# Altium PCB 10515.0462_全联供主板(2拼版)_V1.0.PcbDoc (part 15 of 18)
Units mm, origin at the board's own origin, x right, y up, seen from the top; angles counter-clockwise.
Board outline 282 x 198 mm, 2 copper layers (Top Layer, Bottom Layer); 716 components, 0 nets, 2364 pads, 1800 vias.
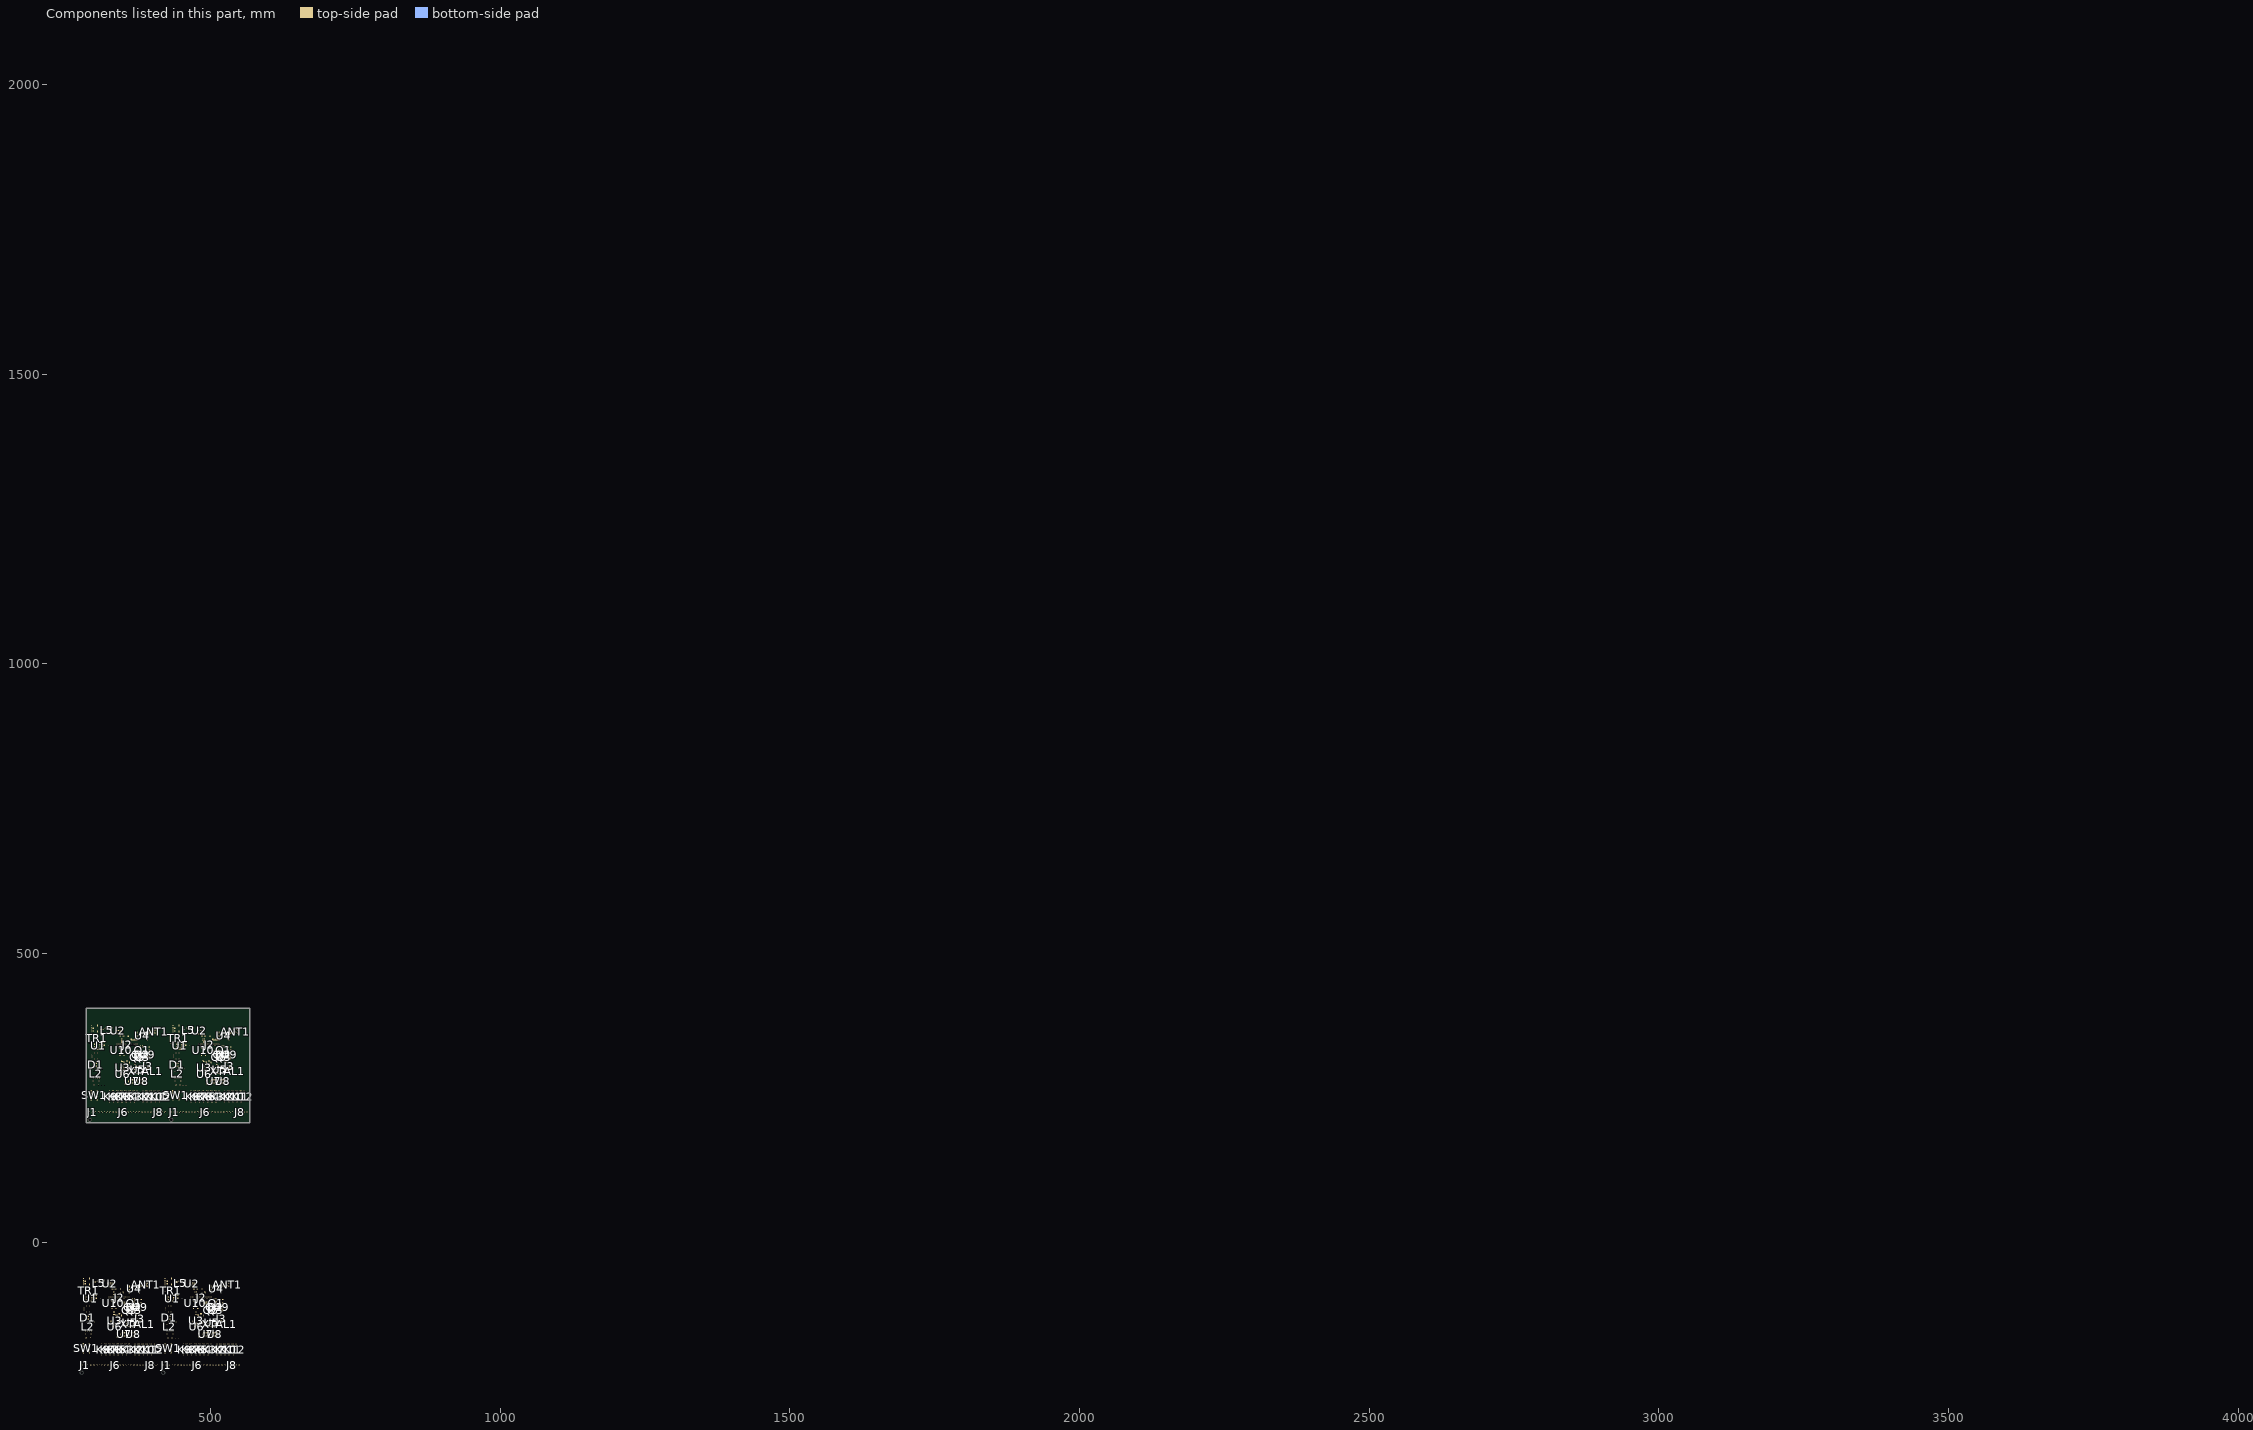
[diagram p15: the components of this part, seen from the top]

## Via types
v1: diameter 0.7, hole 0.4, Top Layer to Bottom Layer, tented both sides, 1800 vias

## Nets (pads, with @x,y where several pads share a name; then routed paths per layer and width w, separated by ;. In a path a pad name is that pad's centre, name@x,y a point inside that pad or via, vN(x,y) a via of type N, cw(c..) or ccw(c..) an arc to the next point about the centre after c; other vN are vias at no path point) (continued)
copper on no net: (continued)
  Bottom Layer w0.65: v1@318.496,-69.089 ccw(c318.496,-68.238) v1@319.098,-68.84 ; v1@318.514,-69.096 ccw(c318.952,-68.658) 318.952,-69.278 ; v1@319.154,-68.797 ccw(c319.893,-68.47) v1(319.893,-69.278) ; v1@319.87,-69.288 ccw(c319.131,-69.615) v1(319.131,-68.807) ; v1@319.875,-69.295 cw(c318.606,-70.565) 320.401,-70.565 ; v1@319.894,-69.303 cw(c319.945,-70.242) 320.61,-69.577 ; v1@320.094,-69.061 ccw(c320.386,-68.769) v1@320.64,-69.094 ; 320.401,-69.788 cw(c321.329,-69.788) v1@320.673,-69.132 ; 322.272,-92.736 cw(c322.272,-95.564) 324.272,-93.564 ccw(c323.526,-94.31) 323.526,-93.255 ccw(c323.526,-92.2) 324.272,-92.946 cw(c322.327,-91.002) 322.327,-93.752 ; 323.841,-92.736 cw(c323.841,-93.995) 324.732,-93.105 ; 323.896,-93.752 ccw(c323.896,-92.571) 324.732,-93.406 ; 324.062,-92.736 321.163,-92.736 320.401,-91.974 320.401,-69.368 319.84,-68.807 v1(319.131,-68.807) ; 324.272,-95.486 ccw(c323.526,-94.74) 324.581,-94.74 ccw(c325.636,-94.74) 324.89,-95.486 ; 324.581,-95.795 324.581,-94.376 323.957,-93.752 320.782,-93.752 319.893,-92.863 319.893,-92.355 ; 324.581,-93.255 320.794,-93.255 319.893,-92.355 ; 325.862,-95.911 327.121,-97.17 ; 327.121,-96.232 cw(c327.121,-97.287) 327.867,-96.541 cw(c328.613,-95.795) 327.558,-95.795 ; 327.259,-96.546 328.529,-97.816 ; 327.558,-95.812 ccw(c329.833,-95.9) 328.223,-97.51 ; 331.704,-92.759 331.704,-89.815 332.657,-88.862 340.15,-88.862 ; 331.704,-92.57 ccw(c332.886,-92.57) 332.05,-93.406 ; 331.704,-91.001 ccw(c334.456,-91.001) 332.51,-92.946 cw(c333.256,-92.2) 332.201,-92.2 cw(c331.146,-92.2) 331.892,-92.946 ccw(c330.353,-91.407) 332.53,-91.407 ; v1@332.125,367.506 ccw(c332.125,368.358) v1@332.727,367.756 ; v1@332.143,367.499 ccw(c332.581,367.937) 332.581,367.318 ; 332.201,-93.255 332.201,-91.974 332.201,-90.588 ; 332.53,-92.927 332.53,-90.259 ; v1@332.783,367.799 ccw(c333.522,368.126) v1(333.522,367.318) ; v1@333.499,367.308 ccw(c332.76,366.981) v1(332.76,367.789) ; v1@333.504,367.3 cw(c332.235,366.031) 334.03,366.031 ; v1@333.523,367.293 cw(c333.574,366.354) 334.239,367.019 ; v1@333.723,367.535 ccw(c334.015,367.827) v1@334.269,367.501 ; 334.03,366.808 cw(c334.957,366.808) v1@334.302,367.464 ; 334.741,-93.255 334.741,-91.477 334.752,-91.466 ; 335.901,343.859 cw(c335.901,341.031) 337.901,343.031 ccw(c337.155,342.285) 337.155,343.34 ccw(c337.155,344.395) 337.901,343.649 cw(c335.956,345.594) 335.956,342.843 ; 337.47,343.859 cw(c337.47,342.6) 338.36,343.491 ; 337.525,342.843 ccw(c337.525,344.025) 338.36,343.189 ; 337.69,343.859 334.792,343.859 334.03,344.621 334.03,367.227 333.469,367.789 v1(332.76,367.789) ; 337.901,341.109 ccw(c337.155,341.855) 338.21,341.855 ccw(c339.265,341.855) 338.519,341.109 ; 338.21,340.8 338.21,342.22 337.586,342.843 334.411,342.843 333.522,343.732 333.522,344.24 ; 338.21,343.34 334.422,343.34 333.522,344.24 ; 339.324,-89.688 340.15,-88.862 ; 339.491,340.684 340.75,339.426 ; 340.14,-88.872 cw(c341.483,-90.216) v1@341.483,-88.316 ; 340.467,-89.307 341.737,-88.037 ; v1@340.729,-88.267 ccw(c341.05,-87.35) 341.737,-88.037 ; 340.75,340.363 cw(c340.75,339.308) 341.496,340.054 cw(c342.242,340.8) 341.187,340.8 ; 340.888,340.049 342.158,338.779 ; 340.902,-88.872 cw(c342.245,-90.216) v1@342.245,-88.316 ; v1@340.902,-88.11 cw(c342.245,-89.454) v1@342.245,-87.554 ; 340.912,-88.862 ccw(c339.569,-87.518) v1@341.469,-87.518 ; 341.186,340.783 ccw(c343.461,340.696) 341.852,339.086 ; v1@341.356,-88.418 cw(c341.861,-88.923) v1@342.232,-88.312 ; v1@341.465,-88.273 ccw(c340.81,-87.617) v1@341.737,-87.617 ; v1@341.468,-88.311 cw(c341.045,-88.859) 341.737,-88.859 ; v1@341.476,-87.536 cw(c340.846,-88.167) v1@341.737,-88.167 ; v1@341.508,-88.291 cw(c343.408,-88.291) v1@342.065,-86.948 ; 341.737,-89.009 cw(c342.463,-89.009) v1@342.252,-88.315 ; v1@341.737,-88.247 cw(c342.463,-88.247) v1@342.252,-87.553 ; 341.801,-89.37 ccw(c340.785,-88.354) v1@342.22,-88.292 ; v1@342.259,-88.27 cw(c342.947,-87.275) v1@341.737,-87.275 ; 345.333,343.837 345.333,346.78 346.285,347.733 353.778,347.733 ; 345.333,344.025 ccw(c346.515,344.025) 345.679,343.189 ; 345.333,345.595 ccw(c348.084,345.595) 346.139,343.649 cw(c346.885,344.395) 345.83,344.395 cw(c344.775,344.395) 345.521,343.649 ccw(c343.981,345.188) 346.158,345.188 ; 345.83,343.34 345.83,344.621 345.83,346.007 ; 346.158,343.669 346.158,346.336 ; v1(347.452,-128.11) 347.497,-128.155 352.926,-128.155 376.027,-128.155 ; 348.37,343.34 348.37,345.118 348.381,345.129 ; v1(348.883,-103.669) v1(352.439,-103.669) 356.735,-103.669 357.231,-104.166 357.231,-113.31 357.231,-113.564 ; v1(348.96,-101.941) v1(352.389,-101.941) v1(355.945,-101.941) 357.866,-101.941 ; 352.953,346.907 353.778,347.733 ; 353.768,347.723 cw(c355.112,346.38) v1@355.112,348.279 ; 354.096,347.288 355.366,348.558 ; v1@354.358,348.328 ccw(c354.679,349.246) 355.366,348.558 ; 354.53,347.723 cw(c355.874,346.38) v1@355.874,348.279 ; v1@354.53,348.485 cw(c355.874,347.142) v1@355.874,349.041 ; 354.541,347.734 ccw(c353.197,349.077) v1@355.097,349.077 ; v1@354.985,348.178 cw(c355.49,347.672) v1@355.861,348.283 ; v1@355.094,348.322 ccw(c354.438,348.978) v1@355.366,348.978 ; v1@355.097,348.285 cw(c354.673,347.737) 355.366,347.737 ; v1@355.105,349.059 cw(c354.474,348.429) v1@355.366,348.429 ; v1@355.137,348.304 cw(c357.037,348.304) v1@355.693,349.648 ; 355.366,347.586 cw(c356.092,347.586) v1@355.881,348.281 ; v1@355.366,348.348 cw(c356.092,348.348) v1@355.881,349.043 ; v1@355.366,349.32 ccw(c356.576,349.32) v1@355.888,348.325 ; 355.429,347.225 ccw(c354.413,348.241) v1@355.849,348.303 ; v1(355.961,-103.658) 356.215,-103.658 357.231,-104.674 ; 358.755,-113.008 cw(c360.098,-113.008) v1@359.149,-112.058 ; 358.755,-111.072 ccw(c360.098,-111.072) v1@359.149,-112.022 ; 358.755,-106.553 cw(c360.14,-106.553) v1@359.161,-105.574 ; 358.755,-104.559 ccw(c360.14,-104.559) v1@359.161,-105.538 ; v1(359.131,-112.04) 359.131,-112.162 360.279,-113.31 ; v1(361.081,308.486) 361.126,308.44 366.555,308.44 389.656,308.44 ; v1(362.512,332.926) v1(366.068,332.926) 370.363,332.926 370.86,332.429 370.86,323.285 370.86,323.031 ; 362.565,-98.324 361.25,-98.324 360.742,-97.816 ; v1(362.589,334.654) v1(366.018,334.654) v1(369.574,334.654) 371.495,334.654 ; 362.819,-127.026 363.581,-126.264 ; 363.199,-127.16 363.581,-126.777 ; v1(363.581,-127.28) 363.581,-126.645 ; 363.581,-120.676 363.581,-120.644 364.184,-120.041 ; 363.581,-119.279 363.581,-119.438 364.184,-120.041 ; 363.964,-127.147 363.594,-126.777 363.581,-126.777 ; 364.47,-127.039 364.356,-127.039 363.581,-126.264 ; 364.548,-113.31 cw(c364.548,-115.491) v1@366.089,-113.949 ; 364.964,-113.31 366.107,-114.453 ; 365.225,-113.571 ccw(c366.039,-112.758) v1@366.106,-113.906 ; v1(365.232,-120.041) 364.216,-120.041 ; v1@365.468,-122.7 cw(c363.927,-124.242) 366.107,-124.242 ; v1@365.468,-122.664 ccw(c363.927,-121.122) 366.107,-121.122 ; v1(366.107,-126.264) 366.107,-118.263 ; 366.107,-119.279 366.107,-119.166 367.01,-118.263 ; 366.107,-117.374 366.996,-118.263 367.01,-118.263 ; v1@366.107,-113.906 ccw(c366.107,-112.585) 367.041,-113.519 ; 366.107,-113.451 v1(366.107,-113.931) 366.107,-114.453 ; v1@366.125,-113.949 cw(c367.667,-115.491) 367.667,-113.31 ; 367.25,-113.31 366.107,-114.453 ; v1(369.59,332.937) 369.844,332.937 370.86,331.921 ; v1(369.931,-113.31) 359.639,-113.31 ; v1(370.727,-117.12) 370.806,-117.041 370.806,-111.038 371.438,-110.406 v1(373.597,-110.406) ; 372.384,323.588 cw(c373.727,323.588) v1@372.777,324.538 ; 372.384,325.523 ccw(c373.727,325.523) v1@372.777,324.573 ; 372.384,330.042 cw(c373.769,330.042) v1@372.79,331.022 ; 372.384,332.037 ccw(c373.769,332.037) v1@372.79,331.057 ; v1(372.76,324.555) 372.76,324.434 373.908,323.285 ; v1(373.614,-112.057) 372.327,-112.057 371.836,-112.548 371.836,-118.009 371.582,-118.263 v1(369.804,-118.263) 367.01,-118.263 ; 374.59,-128.155 cw(c374.59,-130.342) v1@376.136,-128.796 ; v1@376.154,-128.803 cw(c376.154,-130.553) 377.392,-129.316 ; 376.194,338.271 374.879,338.271 374.371,338.779 ; 376.448,309.569 377.21,310.331 ; 376.827,309.436 377.21,309.818 ; 377.152,-130.795 377.152,-129.076 ; 377.152,-129.166 ccw(c379.508,-129.166) 377.842,-130.831 cw(c378.631,-130.042) 377.515,-130.042 cw(c376.399,-130.042) 377.188,-130.831 ; v1(377.21,309.315) 377.21,309.95 ; 377.21,315.919 377.21,315.952 377.813,316.554 ; 377.21,317.316 377.21,317.157 377.813,316.554 ; 377.515,-131.158 377.515,-128.895 376.775,-128.155 376.027,-128.155 ; 377.515,-129.439 377.152,-129.076 ; 377.592,309.449 377.223,309.818 377.21,309.818 ; 378.099,309.556 377.985,309.556 377.21,310.331 ; 378.176,323.285 cw(c378.176,321.105) v1@379.718,322.647 ; 378.593,323.285 379.736,322.142 ; 378.854,323.024 ccw(c379.667,323.838) v1@379.734,322.689 ; v1(378.861,316.554) 377.845,316.554 ; v1@379.097,313.896 cw(c377.555,312.354) 379.736,312.354 ; v1@379.097,313.931 ccw(c377.555,315.473) 379.736,315.473 ; v1(379.736,310.331) 379.736,318.332 ; 379.736,317.316 379.736,317.429 380.639,318.332 ; 379.736,319.221 380.625,318.332 380.639,318.332 ; v1@379.736,322.689 ccw(c379.736,324.01) 380.67,323.076 ; 379.736,323.144 v1(379.736,322.664) 379.736,322.142 ; v1@379.754,322.647 cw(c381.295,321.105) 381.295,323.285 ; v1(379.78,-109.754) 379.78,-106.706 379.78,-102.065 v1(380.091,-101.753) ; 379.78,-102.566 cw(c380.904,-102.566) v1@380.109,-101.771 ; 380.879,323.285 379.736,322.142 ; v1(383.56,323.285) 373.268,323.285 ; v1(384.356,319.475) 384.435,319.555 384.435,325.557 385.067,326.19 v1(387.226,326.19) ; v1(387.243,324.539) 385.956,324.539 385.465,324.047 385.465,318.586 385.211,318.332 v1(383.433,318.332) 380.639,318.332 ; 388.218,308.44 cw(c388.218,306.253) v1@389.765,307.8 ; v1@389.783,307.792 cw(c389.783,306.042) 391.02,307.28 ; 390.781,305.8 390.781,307.519 ; 390.781,307.43 ccw(c393.136,307.43) 391.471,305.764 cw(c392.26,306.553) 391.144,306.553 cw(c390.027,306.553) 390.817,305.764 ; 391.144,305.437 391.144,307.701 390.404,308.44 389.656,308.44 ; 391.144,307.156 390.781,307.519 ; v1(393.408,326.841) 393.408,329.889 393.408,334.531 v1(393.72,334.842) ; 393.408,334.03 cw(c394.533,334.03) v1@393.738,334.825 ; v1@459.496,-69.089 ccw(c459.496,-68.238) v1@460.098,-68.84 ; v1@459.514,-69.096 ccw(c459.952,-68.658) 459.952,-69.278 ; v1@460.154,-68.797 ccw(c460.893,-68.47) v1(460.893,-69.278) ; v1@460.87,-69.288 ccw(c460.131,-69.615) v1(460.131,-68.807) ; v1@460.875,-69.295 cw(c459.606,-70.565) 461.401,-70.565 ; v1@460.894,-69.303 cw(c460.945,-70.242) 461.61,-69.577 ; v1@461.094,-69.061 ccw(c461.386,-68.769) v1@461.64,-69.094 ; 461.401,-69.788 cw(c462.329,-69.788) v1@461.673,-69.132 ; 463.272,-92.736 cw(c463.272,-95.564) 465.272,-93.564 ccw(c464.526,-94.31) 464.526,-93.255 ccw(c464.526,-92.2) 465.272,-92.946 cw(c463.327,-91.002) 463.327,-93.752 ; 464.841,-92.736 cw(c464.841,-93.995) 465.732,-93.105 ; 464.896,-93.752 ccw(c464.896,-92.571) 465.732,-93.406 ; 465.062,-92.736 462.163,-92.736 461.401,-91.974 461.401,-69.368 460.84,-68.807 v1(460.131,-68.807) ; 465.272,-95.486 ccw(c464.526,-94.74) 465.581,-94.74 ccw(c466.636,-94.74) 465.89,-95.486 ; 465.581,-95.795 465.581,-94.376 464.957,-93.752 461.782,-93.752 460.893,-92.863 460.893,-92.355 ; 465.581,-93.255 461.794,-93.255 460.893,-92.355 ; 466.862,-95.911 468.121,-97.17 ; 468.121,-96.232 cw(c468.121,-97.287) 468.867,-96.541 cw(c469.613,-95.795) 468.558,-95.795 ; 468.259,-96.546 469.529,-97.816 ; 468.558,-95.812 ccw(c470.833,-95.9) 469.223,-97.51 ; 472.704,-92.759 472.704,-89.815 473.657,-88.862 481.15,-88.862 ; 472.704,-92.57 ccw(c473.886,-92.57) 473.05,-93.406 ; 472.704,-91.001 ccw(c475.456,-91.001) 473.51,-92.946 cw(c474.256,-92.2) 473.201,-92.2 cw(c472.146,-92.2) 472.892,-92.946 ccw(c471.353,-91.407) 473.53,-91.407 ; v1@473.125,367.506 ccw(c473.125,368.358) v1@473.727,367.756 ; v1@473.143,367.499 ccw(c473.581,367.937) 473.581,367.318 ; 473.201,-93.255 473.201,-91.974 473.201,-90.588 ; 473.53,-92.927 473.53,-90.259 ; v1@473.783,367.799 ccw(c474.522,368.126) v1(474.522,367.318) ; v1@474.499,367.308 ccw(c473.76,366.981) v1(473.76,367.789) ; v1@474.504,367.3 cw(c473.235,366.031) 475.03,366.031 ; v1@474.523,367.293 cw(c474.574,366.354) 475.239,367.019 ; v1@474.723,367.535 ccw(c475.015,367.827) v1@475.269,367.501 ; 475.03,366.808 cw(c475.957,366.808) v1@475.302,367.464 ; 475.741,-93.255 475.741,-91.477 475.752,-91.466 ; 476.901,343.859 cw(c476.901,341.031) 478.901,343.031 ccw(c478.155,342.285) 478.155,343.34 ccw(c478.155,344.395) 478.901,343.649 cw(c476.956,345.594) 476.956,342.843 ; 478.47,343.859 cw(c478.47,342.6) 479.36,343.491 ; 478.525,342.843 ccw(c478.525,344.025) 479.36,343.189 ; 478.69,343.859 475.792,343.859 475.03,344.621 475.03,367.227 474.469,367.789 v1(473.76,367.789) ; 478.901,341.109 ccw(c478.155,341.855) 479.21,341.855 ccw(c480.265,341.855) 479.519,341.109 ; 479.21,340.8 479.21,342.22 478.586,342.843 475.411,342.843 474.522,343.732 474.522,344.24 ; 479.21,343.34 475.422,343.34 474.522,344.24 ; 480.324,-89.688 481.15,-88.862 ; 480.491,340.684 481.75,339.426 ; 481.14,-88.872 cw(c482.483,-90.216) v1@482.483,-88.316 ; 481.467,-89.307 482.737,-88.037 ; v1@481.729,-88.267 ccw(c482.05,-87.35) 482.737,-88.037 ; 481.75,340.363 cw(c481.75,339.308) 482.496,340.054 cw(c483.242,340.8) 482.187,340.8 ; 481.888,340.049 483.158,338.779 ; 481.902,-88.872 cw(c483.245,-90.216) v1@483.245,-88.316 ; v1@481.902,-88.11 cw(c483.245,-89.454) v1@483.245,-87.554 ; 481.912,-88.862 ccw(c480.569,-87.518) v1@482.469,-87.518 ; 482.186,340.783 ccw(c484.461,340.696) 482.852,339.086 ; v1@482.356,-88.418 cw(c482.861,-88.923) v1@483.232,-88.312 ; v1@482.465,-88.273 ccw(c481.81,-87.617) v1@482.737,-87.617 ; v1@482.468,-88.311 cw(c482.045,-88.859) 482.737,-88.859 ; v1@482.476,-87.536 cw(c481.846,-88.167) v1@482.737,-88.167 ; v1@482.508,-88.291 cw(c484.408,-88.291) v1@483.065,-86.948 ; 482.737,-89.009 cw(c483.463,-89.009) v1@483.252,-88.315 ; v1@482.737,-88.247 cw(c483.463,-88.247) v1@483.252,-87.553 ; 482.801,-89.37 ccw(c481.785,-88.354) v1@483.22,-88.292 ; v1@483.259,-88.27 cw(c483.947,-87.275) v1@482.737,-87.275 ; 486.333,343.837 486.333,346.78 487.285,347.733 494.778,347.733 ; 486.333,344.025 ccw(c487.515,344.025) 486.679,343.189 ; 486.333,345.595 ccw(c489.084,345.595) 487.139,343.649 cw(c487.885,344.395) 486.83,344.395 cw(c485.775,344.395) 486.521,343.649 ccw(c484.981,345.188) 487.158,345.188 ; 486.83,343.34 486.83,344.621 486.83,346.007 ; 487.158,343.669 487.158,346.336 ; v1(488.452,-128.11) 488.497,-128.155 493.926,-128.155 517.027,-128.155 ; 489.37,343.34 489.37,345.118 489.381,345.129 ; v1(489.883,-103.669) v1(493.439,-103.669) 497.735,-103.669 498.231,-104.166 498.231,-113.31 498.231,-113.564 ; v1(489.96,-101.941) v1(493.389,-101.941) v1(496.945,-101.941) 498.866,-101.941 ; 493.953,346.907 494.778,347.733 ; 494.768,347.723 cw(c496.112,346.38) v1@496.112,348.279 ; 495.096,347.288 496.366,348.558 ; v1@495.358,348.328 ccw(c495.679,349.246) 496.366,348.558 ; 495.53,347.723 cw(c496.874,346.38) v1@496.874,348.279 ; v1@495.53,348.485 cw(c496.874,347.142) v1@496.874,349.041 ; 495.541,347.734 ccw(c494.197,349.077) v1@496.097,349.077 ; v1@495.985,348.178 cw(c496.49,347.672) v1@496.861,348.283 ; v1@496.094,348.322 ccw(c495.438,348.978) v1@496.366,348.978 ; v1@496.097,348.285 cw(c495.673,347.737) 496.366,347.737 ; v1@496.105,349.059 cw(c495.474,348.429) v1@496.366,348.429 ; v1@496.137,348.304 cw(c498.037,348.304) v1@496.693,349.648 ; 496.366,347.586 cw(c497.092,347.586) v1@496.881,348.281 ; v1@496.366,348.348 cw(c497.092,348.348) v1@496.881,349.043 ; v1@496.366,349.32 ccw(c497.576,349.32) v1@496.888,348.325 ; 496.429,347.225 ccw(c495.413,348.241) v1@496.849,348.303 ; v1(496.961,-103.658) 497.215,-103.658 498.231,-104.674 ; 499.755,-113.008 cw(c501.098,-113.008) v1@500.149,-112.058 ; 499.755,-111.072 ccw(c501.098,-111.072) v1@500.149,-112.022 ; 499.755,-106.553 cw(c501.14,-106.553) v1@500.161,-105.574 ; 499.755,-104.559 ccw(c501.14,-104.559) v1@500.161,-105.538 ; v1(500.131,-112.04) 500.131,-112.162 501.279,-113.31 ; v1(502.081,308.486) 502.126,308.44 507.555,308.44 530.656,308.44 ; v1(503.512,332.926) v1(507.068,332.926) 511.363,332.926 511.86,332.429 511.86,323.285 511.86,323.031 ; 503.565,-98.324 502.25,-98.324 501.742,-97.816 ; v1(503.589,334.654) v1(507.018,334.654) v1(510.574,334.654) 512.495,334.654 ; 503.819,-127.026 504.581,-126.264 ; 504.199,-127.16 504.581,-126.777 ; v1(504.581,-127.28) 504.581,-126.645 ; 504.581,-120.676 504.581,-120.644 505.184,-120.041 ; 504.581,-119.279 504.581,-119.438 505.184,-120.041 ; 504.964,-127.147 504.594,-126.777 504.581,-126.777 ; 505.47,-127.039 505.356,-127.039 504.581,-126.264 ; 505.548,-113.31 cw(c505.548,-115.491) v1@507.089,-113.949 ; 505.964,-113.31 507.107,-114.453 ; 506.225,-113.571 ccw(c507.039,-112.758) v1@507.106,-113.906 ; v1(506.232,-120.041) 505.216,-120.041 ; v1@506.468,-122.7 cw(c504.927,-124.242) 507.107,-124.242 ; v1@506.468,-122.664 ccw(c504.927,-121.122) 507.107,-121.122 ; v1(507.107,-126.264) 507.107,-118.263 ; 507.107,-119.279 507.107,-119.166 508.01,-118.263 ; 507.107,-117.374 507.996,-118.263 508.01,-118.263 ; v1@507.107,-113.906 ccw(c507.107,-112.585) 508.041,-113.519 ; 507.107,-113.451 v1(507.107,-113.931) 507.107,-114.453 ; v1@507.125,-113.949 cw(c508.667,-115.491) 508.667,-113.31 ; 508.25,-113.31 507.107,-114.453 ; v1(510.59,332.937) 510.844,332.937 511.86,331.921 ; v1(510.931,-113.31) 500.639,-113.31 ; v1(511.727,-117.12) 511.806,-117.041 511.806,-111.038 512.438,-110.406 v1(514.597,-110.406) ; 513.384,323.588 cw(c514.727,323.588) v1@513.777,324.538 ; 513.384,325.523 ccw(c514.727,325.523) v1@513.777,324.573 ; 513.384,330.042 cw(c514.769,330.042) v1@513.79,331.022 ; 513.384,332.037 ccw(c514.769,332.037) v1@513.79,331.057 ; v1(513.76,324.555) 513.76,324.434 514.908,323.285 ; v1(514.614,-112.057) 513.327,-112.057 512.836,-112.548 512.836,-118.009 512.582,-118.263 v1(510.804,-118.263) 508.01,-118.263 ; 515.59,-128.155 cw(c515.59,-130.342) v1@517.136,-128.796 ; v1@517.154,-128.803 cw(c517.154,-130.553) 518.392,-129.316 ; 517.194,338.271 515.879,338.271 515.371,338.779 ; 517.448,309.569 518.21,310.331 ; 517.827,309.436 518.21,309.818 ; 518.152,-130.795 518.152,-129.076 ; 518.152,-129.166 ccw(c520.508,-129.166) 518.842,-130.831 cw(c519.631,-130.042) 518.515,-130.042 cw(c517.399,-130.042) 518.188,-130.831 ; v1(518.21,309.315) 518.21,309.95 ; 518.21,315.919 518.21,315.952 518.813,316.554 ; 518.21,317.316 518.21,317.157 518.813,316.554 ; 518.515,-131.158 518.515,-128.895 517.775,-128.155 517.027,-128.155 ; 518.515,-129.439 518.152,-129.076 ; 518.593,309.449 518.223,309.818 518.21,309.818 ; 519.099,309.556 518.985,309.556 518.21,310.331 ; 519.176,323.285 cw(c519.176,321.105) v1@520.718,322.647 ; 519.593,323.285 520.736,322.142 ; 519.854,323.024 ccw(c520.667,323.838) v1@520.734,322.689 ; v1(519.861,316.554) 518.845,316.554 ; v1@520.097,313.896 cw(c518.555,312.354) 520.736,312.354 ; v1@520.097,313.931 ccw(c518.555,315.473) 520.736,315.473 ; v1(520.736,310.331) 520.736,318.332 ; 520.736,317.316 520.736,317.429 521.639,318.332 ; 520.736,319.221 521.625,318.332 521.639,318.332 ; v1@520.736,322.689 ccw(c520.736,324.01) 521.67,323.076 ; 520.736,323.144 v1(520.736,322.664) 520.736,322.142 ; v1@520.754,322.647 cw(c522.295,321.105) 522.295,323.285 ; v1(520.78,-109.754) 520.78,-106.706 520.78,-102.065 v1(521.091,-101.753) ; 520.78,-102.566 cw(c521.904,-102.566) v1@521.109,-101.771 ; 521.879,323.285 520.736,322.142 ; v1(524.56,323.285) 514.268,323.285 ; v1(525.356,319.475) 525.435,319.555 525.435,325.557 526.067,326.19 v1(528.226,326.19) ; v1(528.243,324.539) 526.956,324.539 526.465,324.047 526.465,318.586 526.211,318.332 v1(524.433,318.332) 521.639,318.332 ; 529.218,308.44 cw(c529.218,306.253) v1@530.765,307.8 ; v1@530.783,307.792 cw(c530.783,306.042) 532.02,307.28 ; 531.781,305.8 531.781,307.519 ; 531.781,307.43 ccw(c534.136,307.43) 532.471,305.764 cw(c533.26,306.553) 532.144,306.553 cw(c531.027,306.553) 531.817,305.764 ; 532.144,305.437 532.144,307.701 531.404,308.44 530.656,308.44 ; 532.144,307.156 531.781,307.519 ; v1(534.408,326.841) 534.408,329.889 534.408,334.531 v1(534.72,334.842) ; 534.408,334.03 cw(c535.533,334.03) v1@534.738,334.825 ; v1(319.131,-68.807) 318.66,-69.278 v1(319.893,-69.278) ; 319.893,-92.355 v1(319.893,-69.278) ; 327.121,-97.17 327.121,-95.795 329.142,-97.816 ; 327.121,-97.17 327.767,-97.816 ; 327.121,-96.85 ccw(c326.066,-96.85) 326.812,-96.104 cw(c326.066,-96.85) 327.121,-96.85 ; 327.121,-96.85 cw(c328.176,-96.85) 327.43,-96.104 ccw(c328.176,-96.85) 327.121,-96.85 ; 327.767,-97.816 328.275,-98.324 329.799,-98.324 ; 327.767,-97.816 328.529,-97.816 ; 328.529,-97.816 329.291,-97.816 ; 329.142,-97.816 360.742,-97.816 ; 329.142,-97.816 329.291,-97.816 ; 329.291,-97.816 329.799,-98.324 ; 329.799,-98.324 363.327,-98.324 ; 332.201,-90.588 332.201,-89.953 332.847,-89.307 333.482,-89.307 341.229,-89.307 341.737,-88.799 341.737,-88.037 ; 332.201,-90.588 332.53,-90.259 ; 332.53,-90.259 333.101,-89.688 341.483,-89.688 342.245,-88.926 v1(342.245,-86.767) ; v1(332.76,367.789) 332.289,367.318 v1(333.522,367.318) ; 333.522,344.24 v1(333.522,367.318) ; 340.15,-88.862 v1(342.245,-86.767) ; 340.75,339.426 340.75,340.8 342.77,338.779 ; 340.75,339.426 341.396,338.779 ; 340.75,339.745 ccw(c339.695,339.745) 340.441,340.491 cw(c339.695,339.745) 340.75,339.745 ; 340.75,339.745 cw(c341.805,339.745) 341.059,340.491 ccw(c341.805,339.745) 340.75,339.745 ; 341.396,338.779 341.904,338.271 343.428,338.271 ; 341.396,338.779 342.158,338.779 ; 341.737,-88.037 v1@341.737,-87.275 ; v1@341.737,-87.275 v1(342.245,-86.767) ; 342.158,338.779 342.92,338.779 ; 342.77,338.779 374.371,338.779 ; 342.77,338.779 342.92,338.779 ; 342.92,338.779 343.428,338.271 ; 343.428,338.271 376.956,338.271 ; 345.83,346.007 345.83,346.642 346.476,347.288 347.111,347.288 354.858,347.288 355.366,347.796 355.366,348.558 ; 345.83,346.007 346.158,346.336 ; 346.158,346.336 346.73,346.907 355.112,346.907 355.874,347.669 v1(355.874,349.828) ; 353.778,347.733 v1(355.874,349.828) ; 355.366,348.558 355.366,349.32 v1(355.874,349.828) ; 357.231,-113.564 357.231,-114.072 357.612,-114.453 358.12,-114.453 ; 357.231,-113.564 358.12,-114.453 ; 357.866,-101.941 358.69,-101.941 359.143,-102.395 v1(359.143,-105.556) 359.143,-112.814 359.639,-113.31 ; 357.866,-101.941 358.755,-102.83 358.755,-113.056 359.009,-113.31 359.639,-113.31 ; 358.12,-114.453 362.311,-114.453 362.565,-114.453 ; 360.742,-97.816 363.454,-97.816 363.962,-98.324 ; 362.565,-114.453 363.581,-115.469 ; 362.565,-114.453 363.2,-114.453 363.581,-114.834 363.581,-115.469 ; 363.327,-98.324 363.708,-98.705 v1(366.121,-101.118) 366.121,-100.483 363.962,-98.324 ; 363.327,-98.324 363.962,-98.324 ; 363.581,-126.777 363.581,-126.645 ; 363.581,-126.645 363.581,-126.264 ; 363.581,-126.264 v1(363.581,-120.041) ; v1(363.581,-120.041) 364.216,-120.041 ; v1(363.581,-120.041) 363.581,-115.469 ; 364.184,-120.041 364.216,-120.041 ; 364.184,-120.041 364.216,-120.041 ; 366.107,-118.263 367.01,-118.263 ; 366.107,-118.263 366.107,-114.453 ; 370.86,323.031 370.86,322.523 371.241,322.142 371.749,322.142 ; 370.86,323.031 371.749,322.142 ; 371.495,334.654 372.318,334.654 372.772,334.2 v1(372.772,331.039) 372.772,323.781 373.268,323.285 ; 371.495,334.654 372.384,333.765 372.384,323.539 372.638,323.285 373.268,323.285 ; 371.749,322.142 375.94,322.142 376.194,322.142 ; 374.371,338.779 377.083,338.779 377.591,338.271 ; 376.027,-128.155 376.231,-128.155 377.152,-129.076 ; 376.194,322.142 377.21,321.126 ; 376.194,322.142 376.829,322.142 377.21,321.761 377.21,321.126 ; 376.956,338.271 377.337,337.89 v1(379.75,335.477) 379.75,336.112 377.591,338.271 ; 376.956,338.271 377.591,338.271 ; 377.21,309.818 377.21,309.95 ; 377.21,309.95 377.21,310.331 ; 377.21,310.331 v1(377.21,316.554) ; v1(377.21,316.554) 377.845,316.554 ; v1(377.21,316.554) 377.21,321.126 ; 377.813,316.554 377.845,316.554 ; 377.813,316.554 377.845,316.554 ; 379.736,318.332 380.639,318.332 ; 379.736,318.332 379.736,322.142 ; 389.656,308.44 389.86,308.44 390.781,307.519 ; v1(460.131,-68.807) 459.66,-69.278 v1(460.893,-69.278) ; 460.893,-92.355 v1(460.893,-69.278) ; 468.121,-97.17 468.121,-95.795 470.142,-97.816 ; 468.121,-97.17 468.767,-97.816 ; 468.121,-96.85 ccw(c467.066,-96.85) 467.812,-96.104 cw(c467.066,-96.85) 468.121,-96.85 ; 468.121,-96.85 cw(c469.176,-96.85) 468.43,-96.104 ccw(c469.176,-96.85) 468.121,-96.85 ; 468.767,-97.816 469.275,-98.324 470.799,-98.324 ; 468.767,-97.816 469.529,-97.816 ; 469.529,-97.816 470.291,-97.816 ; 470.142,-97.816 501.742,-97.816 ; 470.142,-97.816 470.291,-97.816 ; 470.291,-97.816 470.799,-98.324 ; 470.799,-98.324 504.327,-98.324 ; 473.201,-90.588 473.201,-89.953 473.847,-89.307 474.482,-89.307 482.229,-89.307 482.737,-88.799 482.737,-88.037 ; 473.201,-90.588 473.53,-90.259 ; 473.53,-90.259 474.101,-89.688 482.483,-89.688 483.245,-88.926 v1(483.245,-86.767) ; v1(473.76,367.789) 473.289,367.318 v1(474.522,367.318) ; 474.522,344.24 v1(474.522,367.318) ; 481.15,-88.862 v1(483.245,-86.767) ; 481.75,339.426 481.75,340.8 483.77,338.779 ; 481.75,339.426 482.396,338.779 ; 481.75,339.745 ccw(c480.695,339.745) 481.441,340.491 cw(c480.695,339.745) 481.75,339.745 ; 481.75,339.745 cw(c482.805,339.745) 482.059,340.491 ccw(c482.805,339.745) 481.75,339.745 ; 482.396,338.779 482.904,338.271 484.428,338.271 ; 482.396,338.779 483.158,338.779 ; 482.737,-88.037 v1@482.737,-87.275 ; v1@482.737,-87.275 v1(483.245,-86.767) ; 483.158,338.779 483.92,338.779 ; 483.77,338.779 515.371,338.779 ; 483.77,338.779 483.92,338.779 ; 483.92,338.779 484.428,338.271 ; 484.428,338.271 517.956,338.271 ; 486.83,346.007 486.83,346.642 487.476,347.288 488.111,347.288 495.858,347.288 496.366,347.796 496.366,348.558 ; 486.83,346.007 487.158,346.336 ; 487.158,346.336 487.73,346.907 496.112,346.907 496.874,347.669 v1(496.874,349.828) ; 494.778,347.733 v1(496.874,349.828) ; 496.366,348.558 496.366,349.32 v1(496.874,349.828) ; 498.231,-113.564 498.231,-114.072 498.612,-114.453 499.12,-114.453 ; 498.231,-113.564 499.12,-114.453 ; 498.866,-101.941 499.69,-101.941 500.143,-102.395 v1(500.143,-105.556) 500.143,-112.814 500.639,-113.31 ; 498.866,-101.941 499.755,-102.83 499.755,-113.056 500.009,-113.31 500.639,-113.31 ; 499.12,-114.453 503.311,-114.453 503.565,-114.453 ; 501.742,-97.816 504.454,-97.816 504.962,-98.324 ; 503.565,-114.453 504.581,-115.469 ; 503.565,-114.453 504.2,-114.453 504.581,-114.834 504.581,-115.469 ; 504.327,-98.324 504.708,-98.705 v1(507.121,-101.118) 507.121,-100.483 504.962,-98.324 ; 504.327,-98.324 504.962,-98.324 ; 504.581,-126.777 504.581,-126.645 ; 504.581,-126.645 504.581,-126.264 ; 504.581,-126.264 v1(504.581,-120.041) ; v1(504.581,-120.041) 505.216,-120.041 ; v1(504.581,-120.041) 504.581,-115.469 ; 505.184,-120.041 505.216,-120.041 ; 505.184,-120.041 505.216,-120.041 ; 507.107,-118.263 508.01,-118.263 ; 507.107,-118.263 507.107,-114.453 ; 511.86,323.031 511.86,322.523 512.241,322.142 512.749,322.142 ; 511.86,323.031 512.749,322.142 ; 512.495,334.654 513.318,334.654 513.772,334.2 v1(513.772,331.039) 513.772,323.781 514.268,323.285 ; 512.495,334.654 513.384,333.765 513.384,323.539 513.638,323.285 514.268,323.285 ; 512.749,322.142 516.94,322.142 517.194,322.142 ; 515.371,338.779 518.083,338.779 518.591,338.271 ; 517.027,-128.155 517.231,-128.155 518.152,-129.076 ; 517.194,322.142 518.21,321.126 ; 517.194,322.142 517.829,322.142 518.21,321.761 518.21,321.126 ; 517.956,338.271 518.337,337.89 v1(520.75,335.477) 520.75,336.112 518.591,338.271 ; 517.956,338.271 518.591,338.271 ; 518.21,309.818 518.21,309.95 ; 518.21,309.95 518.21,310.331 ; 518.21,310.331 v1(518.21,316.554) ; v1(518.21,316.554) 518.845,316.554 ; v1(518.21,316.554) 518.21,321.126 ; 518.813,316.554 518.845,316.554 ; 518.813,316.554 518.845,316.554 ; 520.736,318.332 521.639,318.332 ; 520.736,318.332 520.736,322.142 ; 530.656,308.44 530.86,308.44 531.781,307.519 ; v1@341.478,-87.538 cw(c341.017,-88.091) 341.737,-88.091 ccw(c341.017,-88.091) v1@341.478,-87.538 ; v1@355.106,349.058 cw(c354.646,348.504) 355.366,348.504 ccw(c354.646,348.504) v1@355.106,349.058 ; v1@482.478,-87.538 cw(c482.017,-88.091) 482.737,-88.091 ccw(c482.017,-88.091) v1@482.478,-87.538 ; v1@496.106,349.058 cw(c495.646,348.504) 496.366,348.504 ccw(c495.646,348.504) v1@496.106,349.058
  Bottom Layer w1: 273.411,-206.147 277.081,-209.817 277.081,-210.984 ; 273.983,-206.718 273.983,-205.512 ; 273.983,-144.488 273.983,-205.512 ; 274.975,-207.711 cw(c271.702,-210.984) 276.331,-210.984 ccw(c274.52,-210.984) 275.801,-209.704 ccw(c277.081,-208.424) 277.081,-210.234 ; 276.682,-209.418 cw(c275.116,-210.984) 277.331,-210.984 ; 277.081,-223.787 277.221,-223.927 ; 286.111,-136.551 281.92,-136.551 273.411,-145.06 273.411,-207.315 277.081,-210.984 ; 287.04,230.448 290.71,226.779 290.71,225.611 ; 287.611,229.877 287.611,231.083 ; 287.611,292.107 287.611,231.083 ; 288.604,228.885 cw(c285.33,225.611) 289.96,225.611 ccw(c288.149,225.611) 289.429,226.891 ccw(c290.71,228.172) 290.71,226.361 ; 290.311,227.177 cw(c288.745,225.611) 290.96,225.611 ; 290.71,212.809 290.85,212.668 ; 299.74,300.044 295.549,300.044 287.04,291.535 287.04,229.281 290.71,225.611 ; 414.411,-206.147 418.081,-209.817 418.081,-210.984 ; 414.983,-206.718 414.983,-205.512 ; 414.983,-144.488 414.983,-205.512 ; 415.975,-207.711 cw(c412.702,-210.984) 417.331,-210.984 ccw(c415.52,-210.984) 416.801,-209.704 ccw(c418.081,-208.424) 418.081,-210.234 ; 417.682,-209.418 cw(c416.116,-210.984) 418.331,-210.984 ; 418.081,-223.787 418.221,-223.927 ; 427.111,-136.551 422.92,-136.551 414.411,-145.06 414.411,-207.315 418.081,-210.984 ; 428.04,230.448 431.71,226.779 431.71,225.611 ; 428.611,229.877 428.611,231.083 ; 428.611,292.107 428.611,231.083 ; 429.604,228.885 cw(c426.33,225.611) 430.96,225.611 ccw(c429.149,225.611) 430.429,226.891 ccw(c431.71,228.172) 431.71,226.361 ; 431.311,227.177 cw(c429.745,225.611) 431.96,225.611 ; 431.71,212.809 431.85,212.668 ; 440.74,300.044 436.549,300.044 428.04,291.535 428.04,229.281 431.71,225.611 ; 273.983,-205.512 277.081,-208.61 277.081,-210.984 ; 287.611,231.083 290.71,227.985 290.71,225.611 ; 414.983,-205.512 418.081,-208.61 418.081,-210.984 ; 428.611,231.083 431.71,227.985 431.71,225.611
